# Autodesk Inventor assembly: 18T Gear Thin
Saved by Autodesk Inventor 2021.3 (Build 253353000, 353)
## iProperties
Created: 2022-05
Part Number: 18T Gear Thin
Document SubType Name: Assembly
Designer: Administrator
Title: 18T Gear Thin v15
Author: Administrator
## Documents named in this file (4)
- c:\worker\convert-fusion-r03\tmp\job-1\185\output\files\0fa6b6d8-5ae5-4a2f-92c7-634827d88ab4\614356e8-fe26-469c-bf44-84c217636aa2.iam
- c:\worker\convert-fusion-r03\tmp\job-1\185\output\files\0fa6b6d8-5ae5-4a2f-92c7-634827d88ab4\Bearing 3mm ID 6mm OD v3.iam
- c:\worker\convert-fusion-r03\tmp\job-1\185\output\files\0fa6b6d8-5ae5-4a2f-92c7-634827d88ab4\m3_10mm v1.iam
- c:\worker\convert-fusion-r03\tmp\job-1\185\output\files\0fa6b6d8-5ae5-4a2f-92c7-634827d88ab4\Part6.ipt
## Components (3 placed, 3 different names)
1. Bearing 3mm ID 6mm OD v3:1 [sub-assembly]
2. m3_10mm v1:1 [sub-assembly]
3. Part6
